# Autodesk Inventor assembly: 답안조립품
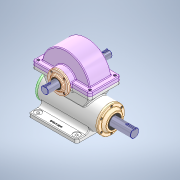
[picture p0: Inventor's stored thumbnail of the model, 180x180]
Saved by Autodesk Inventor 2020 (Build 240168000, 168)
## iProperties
Created: 2023-12
Part Number: 답안조립품
Document SubType Name: Assembly
Designer: oem
Author: oem
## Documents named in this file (14)
- C:\Users\oem\Desktop\631208V1009\답안조립품.iam
- C:\Users\oem\Desktop\631208V1009\본체.ipt
- C:\Users\oem\Desktop\631208V1009\깊은 홈 볼 베어링 6209.ipt
- C:\Users\oem\Desktop\631208V1009\웜 샤프트.ipt
- C:\Users\oem\Desktop\631208V1009\뒤커버.ipt
- C:\Users\oem\Desktop\631208V1009\앞커버.ipt
- C:\Users\oem\Desktop\631208V1009\육각 소켓 머리 볼트 M5 x 12.ipt
- C:\Users\oem\Desktop\631208V1009\오일 실 35 55 11.ipt
- C:\Users\oem\Desktop\631208V1009\깊은 홈 볼 베어링 6206.ipt
- C:\Users\oem\Desktop\631208V1009\웜 휠.ipt
- C:\Users\oem\Desktop\631208V1009\본체 커버.ipt
- C:\Users\oem\Desktop\631208V1009\육각 소켓 머리 볼트 M6 x 20.ipt
- C:\Users\oem\Desktop\631208V1009\서브커버.ipt
- C:\Users\oem\Desktop\631208V1009\오일 실 30 42 7.ipt
